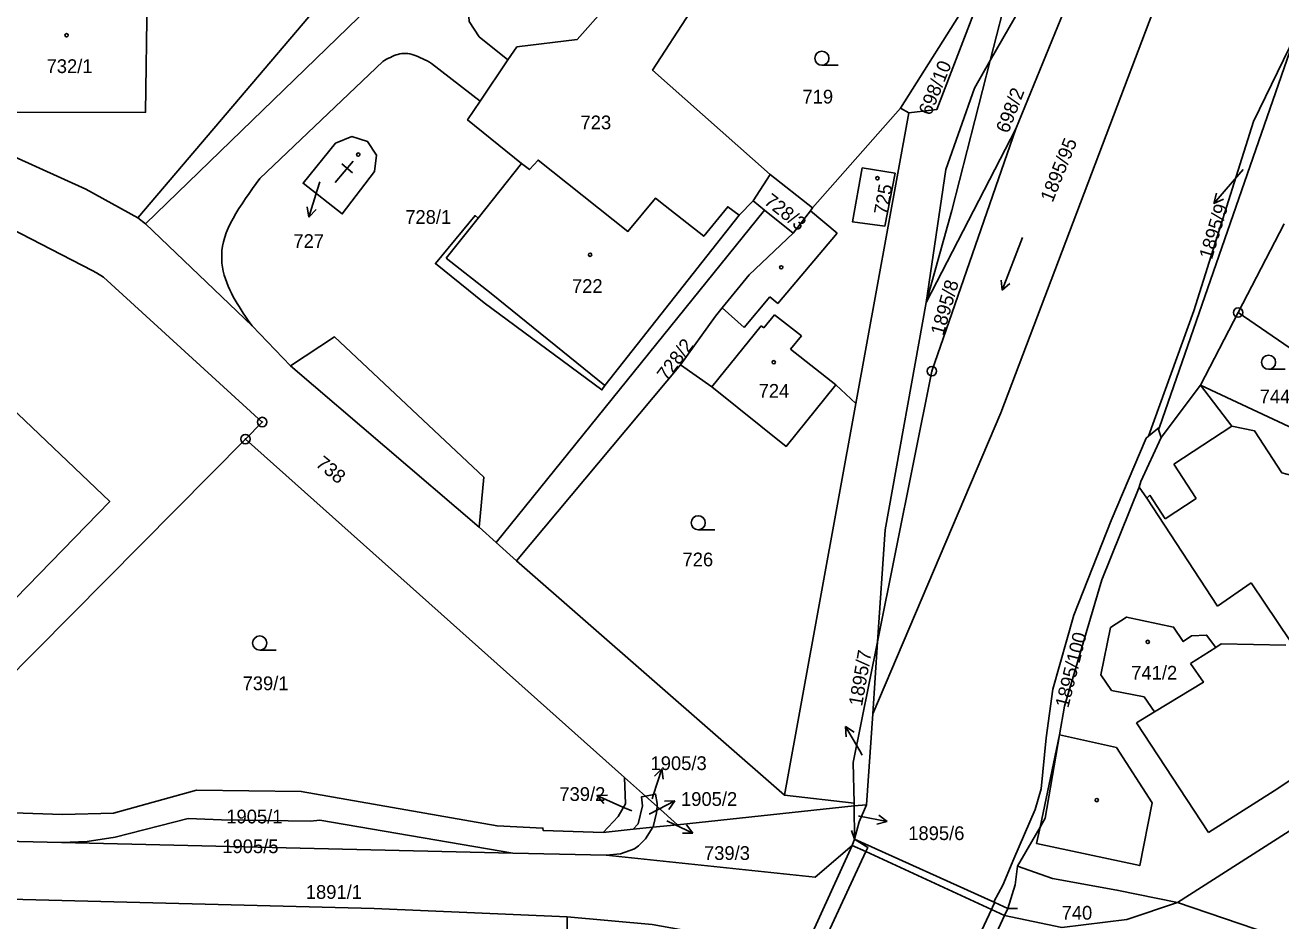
# Model space of a CAD drawing. Extents: x -587171 to -555306, y -1167727 to -1074732.
# Drawn here: x -560966.9 to -560833.4, y -1078357 to -1078261.8 of the extents above; entities that cross this region are included whole.
import ezdxf

# ---------------------------------------------------------------- set-up
doc = ezdxf.new("R2010")
doc.units = 0
for name, color, linetype in [('Hranice parcel', 7, 'Continuous'), ('Parcelní čísla', 7, 'Continuous'), ('Pop  PČ popisy', 7, 'Continuous'), ('Vnitřní kresba', 7, 'Continuous'), ('Značky bodu BP', 7, 'Continuous'), ('Značky budov', 7, 'Continuous'), ('Značky kultur', 7, 'Continuous')]:
    doc.layers.add(name, color=color, linetype=linetype)

msp = doc.modelspace()

# ---------------------------------------------------------------- linework, layer by layer
at = {"layer": 'Hranice parcel'}
for p, q in [((-560873.8, -1078270.61), (-560859.42, -1078247.75)), ((-560861.57, -1078272.8), (-560852.78, -1078251.3)), ((-560936.7, -1078260.89), (-560954.86, -1078282.28)), ((-560831.84, -1078262.87), (-560846.3, -1078304.51)), ((-560883.15, -1078281.2), (-560873.8, -1078270.61)), ((-560878.56, -1078302), (-560872.93, -1078271.11)), ((-560872.93, -1078271.11), (-560873.8, -1078270.61)), ((-560861.57, -1078272.8), (-560871.09, -1078291.27)), ((-560889.47, -1078280.48), (-560887.66, -1078277.67)), ((-560887.66, -1078277.67), (-560883.15, -1078281.2)), ((-560890.95, -1078281.97), (-560889.47, -1078280.48)), ((-560888.28, -1078281.44), (-560889.47, -1078280.48)), ((-560916.78, -1078316.76), (-560888.28, -1078281.44)), ((-560885.23, -1078283.9), (-560888.28, -1078281.44)), ((-560837.93, -1078292.34), (-560833.04, -1078282.89)), ((-560841.92, -1078300.06), (-560837.93, -1078292.34)), ((-560897.18, -1078297.9), (-560914.63, -1078318.72)), ((-560841.92, -1078300.06), (-560846.09, -1078305.62)), ((-560810.03, -1078314.95), (-560841.92, -1078300.06)), ((-560886.14, -1078343.63), (-560878.56, -1078302)), ((-560847.44, -1078305.46), (-560846.3, -1078304.51)), ((-560943.44, -1078305.78), (-560903.14, -1078341.76)), ((-560846.09, -1078305.62), (-560848.28, -1078310.28)), ((-560916.78, -1078316.76), (-560914.63, -1078318.72)), ((-560914.63, -1078318.72), (-560886.14, -1078343.63)), ((-560852.4, -1078320.73), (-560856.39, -1078334.17)), ((-560876.76, -1078334.99), (-560876.25, -1078327.32)), ((-560844.37, -1078355.05), (-560801.81, -1078327.78)), ((-560876.76, -1078334.99), (-560877.41, -1078344.64)), ((-560903.14, -1078341.76), (-560900.93, -1078343.73)), ((-560878.75, -1078344.48), (-560886.14, -1078343.63)), ((-560900.93, -1078343.73), (-560899.68, -1078344.85)), ((-560899.68, -1078344.85), (-560897.53, -1078346.77)), ((-560897.53, -1078346.77), (-560878.75, -1078344.78)), ((-560878.75, -1078344.78), (-560878.75, -1078344.48)), ((-560878.75, -1078344.78), (-560877.41, -1078344.64)), ((-560878.75, -1078344.78), (-560878.69, -1078348.32)), ((-560905.4, -1078347.6), (-560902.21, -1078347.26)), ((-560902.21, -1078347.26), (-560900.13, -1078347.04)), ((-560900.13, -1078347.04), (-560897.53, -1078346.77)), ((-560862.39, -1078355.68), (-560863.77, -1078355.05)), ((-560862.39, -1078355.68), (-560862.76, -1078356.41)), ((-560844.37, -1078355.05), (-560831.14, -1078359.52)), ((-560862.76, -1078356.41), (-560867.32, -1078366.23))]:
    msp.add_line(p, q, dxfattribs=at)
for points in [[(-560876.76, -1078334.99), (-560863.14, -1078303), (-560843.89, -1078252.14), (-560835.48, -1078230.5)], [(-560975.6, -1078271.08), (-560969.5, -1078271.07), (-560954.05, -1078271.05), (-560953.89, -1078258.74), (-560953.94, -1078254.36), (-560962.01, -1078249.46)], [(-560857.54, -1078249.2), (-560865.13, -1078258.18), (-560869.96, -1078270.77), (-560872.93, -1078271.11)], [(-560918.28, -1078255.05), (-560919.83, -1078258.61), (-560919.65, -1078261.4), (-560918.59, -1078263.02), (-560915.56, -1078265.47)], [(-560915.56, -1078265.47), (-560914.58, -1078264.09), (-560908.19, -1078263.31), (-560902.01, -1078256.32), (-560896.18, -1078260.41)], [(-560871.09, -1078291.27), (-560868.35, -1078281.5), (-560864.28, -1078265.55), (-560862.94, -1078260.3), (-560858.64, -1078255.73)], [(-560896.18, -1078260.41), (-560900.17, -1078266.58), (-560887.66, -1078277.67)], [(-560847.44, -1078305.46), (-560842.64, -1078292.16), (-560836.31, -1078272.04), (-560831.84, -1078262.87)], [(-560915.56, -1078265.47), (-560918.47, -1078269.87), (-560919.82, -1078271.87), (-560914.09, -1078276.49)], [(-560975.6, -1078271.08), (-560975.58, -1078272.35), (-560960.38, -1078279.23), (-560954.86, -1078282.28)], [(-560876.25, -1078327.32), (-560870.47, -1078298.56), (-560861.57, -1078272.8)], [(-560933.87, -1078274.34), (-560937.3, -1078278.6), (-560933.14, -1078281.85), (-560929.72, -1078277.35), (-560929.51, -1078275.62), (-560930.45, -1078274.14), (-560932.11, -1078273.63), (-560933.87, -1078274.34)], [(-560914.09, -1078276.49), (-560918.7, -1078282.3), (-560919.03, -1078282.03), (-560923.24, -1078287.14), (-560918.05, -1078291.3), (-560905.55, -1078300.56), (-560905.24, -1078300.1), (-560890.95, -1078281.97)], [(-560890.95, -1078281.97), (-560892.18, -1078281.1), (-560894.73, -1078284.22), (-560898.84, -1078280.99), (-560899.85, -1078280.17), (-560902.78, -1078283.71), (-560912.33, -1078276.14), (-560913.26, -1078277.15), (-560914.09, -1078276.49)], [(-560877.88, -1078276.96), (-560874.38, -1078277.53), (-560875.48, -1078283.16), (-560878.9, -1078282.7), (-560877.88, -1078276.96)], [(-560980.94, -1078278.9), (-560975.34, -1078279.89), (-560974.92, -1078280.03), (-560959.72, -1078287.86), (-560959.25, -1078288.13), (-560958.53, -1078288.59), (-560941.65, -1078303.97), (-560943.44, -1078305.78)], [(-560954.86, -1078282.28), (-560954.07, -1078282.89), (-560942.73, -1078293.75), (-560938.66, -1078298.01), (-560933.98, -1078294.93), (-560918.09, -1078309.84), (-560918.58, -1078315.14), (-560916.78, -1078316.76)], [(-560883.15, -1078281.2), (-560883.39, -1078281.51), (-560885.23, -1078283.9)], [(-560885.23, -1078283.9), (-560889.91, -1078288.32), (-560892.75, -1078291.85), (-560893.46, -1078292.72), (-560897.18, -1078297.9)], [(-560991.5, -1078345.99), (-560990.38, -1078345.81), (-560957.85, -1078312.42), (-560979.66, -1078291.65), (-560986.56, -1078298.77), (-560970.59, -1078314.29), (-560976.42, -1078320.26), (-560989.21, -1078333.37), (-561008.36, -1078315.68), (-561001.24, -1078300.34), (-561005.51, -1078298.23)], [(-560871.09, -1078291.27), (-560875.45, -1078315.42), (-560876.25, -1078327.32)], [(-560837.93, -1078292.34), (-560828.78, -1078298.59), (-560810.03, -1078314.95)], [(-560897.18, -1078297.9), (-560893.86, -1078300.22), (-560885.98, -1078306.57), (-560880.7, -1078300.01), (-560878.56, -1078302)], [(-560811.37, -1078328.88), (-560816.43, -1078331.54), (-560823.11, -1078321.25), (-560824.77, -1078322.33), (-560825.94, -1078320.54), (-560825.02, -1078319.94), (-560825.21, -1078319.65), (-560826.12, -1078320.26), (-560830.32, -1078313.81), (-560829.97, -1078312.53), (-560829.83, -1078312.57), (-560829.7, -1078312.12), (-560831.73, -1078311.54), (-560831.41, -1078310.38), (-560831.28, -1078310.42), (-560831.15, -1078309.95), (-560833.27, -1078309.36), (-560836.18, -1078304.91), (-560838.58, -1078304.42), (-560841.92, -1078300.06)], [(-560846.3, -1078304.51), (-560846.39, -1078304.77), (-560846.09, -1078305.62)], [(-560943.44, -1078305.78), (-560980.48, -1078343.18), (-560981.81, -1078345.03)], [(-560863.77, -1078355.05), (-560863.85, -1078354.91), (-560862.95, -1078353.19), (-560861.78, -1078350.38), (-560859.5, -1078345.14), (-560858.87, -1078342.95), (-560858.34, -1078337.52), (-560857.63, -1078332.36), (-560855.4, -1078324.5), (-560851.41, -1078314.44), (-560847.7, -1078305.67), (-560847.44, -1078305.46)], [(-560848.28, -1078310.28), (-560848.43, -1078310.88), (-560852.4, -1078320.73)], [(-560846.8, -1078334.77), (-560847.93, -1078333.17), (-560851.38, -1078332.5), (-560852.52, -1078330.85), (-560851.51, -1078325.81), (-560849.79, -1078324.7), (-560844.78, -1078325.76), (-560843.76, -1078327.3), (-560842.89, -1078326.69), (-560841.28, -1078326.61), (-560840.31, -1078327.93), (-560842.98, -1078329.63)], [(-560876.25, -1078327.32), (-560878.83, -1078340.15), (-560878.75, -1078344.48)], [(-560842.98, -1078329.63), (-560841.62, -1078331.63), (-560846.8, -1078334.77)], [(-560856.39, -1078334.17), (-560856.91, -1078337.2), (-560858.42, -1078346.07)], [(-560905.4, -1078347.6), (-560903.81, -1078345.91), (-560903.03, -1078344.54), (-560903.14, -1078341.76)], [(-560981.81, -1078345.03), (-560962.87, -1078345.67), (-560957.44, -1078345.55), (-560948.62, -1078343.1), (-560937.51, -1078343.23), (-560916.68, -1078346.89), (-560911.81, -1078347.13), (-560911.8, -1078347.38), (-560905.4, -1078347.6)], [(-560900.93, -1078343.73), (-560899.85, -1078343.51), (-560899.66, -1078344.52), (-560899.68, -1078344.85)], [(-560902.21, -1078347.26), (-560901.7, -1078346.66), (-560901.22, -1078344.78), (-560901.34, -1078343.82), (-560900.93, -1078343.73)], [(-560899.68, -1078344.85), (-560899.73, -1078345.52), (-560900.11, -1078347.01), (-560900.13, -1078347.04)], [(-560877.41, -1078344.64), (-560878.19, -1078346.45), (-560878.69, -1078348.32)], [(-560963, -1078348.67), (-560960.26, -1078348.57), (-560957.28, -1078348.11), (-560949.51, -1078346.12), (-560945.98, -1078346.24), (-560936.53, -1078346.39), (-560935.53, -1078346.29), (-560915.01, -1078349.78)], [(-560858.42, -1078346.07), (-560858.98, -1078347.04), (-560861.37, -1078351.19)], [(-560915.01, -1078349.78), (-560905.1, -1078350.01), (-560903.57, -1078349.86), (-560902.08, -1078349.33), (-560901.66, -1078349.02), (-560900.93, -1078348.26), (-560900.13, -1078347.04)], [(-560986.22, -1078347.96), (-560984.24, -1078348.15), (-560976.6, -1078348.33), (-560963, -1078348.67)], [(-560915.01, -1078349.78), (-560936.14, -1078349.3), (-560963, -1078348.67)], [(-560878.69, -1078348.32), (-560877.29, -1078349.19), (-560877.5, -1078349.63), (-560883.75, -1078363.16), (-560883.95, -1078363.58), (-560884.1, -1078363.92), (-560885.12, -1078366.27), (-560887.52, -1078371.1), (-560889.77, -1078371.49), (-560902.77, -1078373.74)], [(-560878.69, -1078348.32), (-560878.94, -1078348.97), (-560884.6, -1078361.4)], [(-560861.37, -1078351.19), (-560861.63, -1078353.15), (-560862.39, -1078355.68)], [(-560844.37, -1078355.05), (-560850.81, -1078353.71), (-560857.67, -1078352.5), (-560861.37, -1078351.19)], [(-560869.31, -1078370.59), (-560870.63, -1078369.61), (-560870.46, -1078369.24), (-560864.14, -1078355.77), (-560863.91, -1078355.28), (-560863.77, -1078355.05)], [(-560862.76, -1078356.41), (-560856.66, -1078357.68), (-560849.77, -1078356.84), (-560844.37, -1078355.05)], [(-560909.29, -1078359.53), (-560909.25, -1078356.56), (-560900.21, -1078357.39), (-560892.88, -1078358.7), (-560887.14, -1078360.42), (-560884.6, -1078361.4)]]:
    msp.add_lwpolyline(points, dxfattribs=at)
at = {"layer": 'Pop  PČ popisy'}
for p, q in [((-560837.39, -1078277.14), (-560838.54, -1078278.46)), ((-560935.81, -1078279.33), (-560936.69, -1078282.2)), ((-560935.54, -1078278.45), (-560935.81, -1078279.33)), ((-560838.54, -1078278.46), (-560840.51, -1078280.73)), ((-560840.51, -1078280.73), (-560840.23, -1078279.64)), ((-560840.51, -1078280.73), (-560839.47, -1078280.3)), ((-560936.69, -1078282.2), (-560936.87, -1078281.1)), ((-560936.69, -1078282.2), (-560935.92, -1078281.39)), ((-560878.15, -1078338.92), (-560879.65, -1078336.32)), ((-560879.65, -1078336.32), (-560878.72, -1078336.94)), ((-560879.65, -1078336.32), (-560879.58, -1078337.44)), ((-560877.89, -1078339.38), (-560878.15, -1078338.92)), ((-560900.11, -1078343.67), (-560899.18, -1078340.82)), ((-560899.18, -1078340.82), (-560899.97, -1078341.61)), ((-560899.18, -1078340.82), (-560899.02, -1078341.92)), ((-560906.07, -1078343.67), (-560904.95, -1078343.62)), ((-560903.33, -1078344.89), (-560906.07, -1078343.67)), ((-560906.07, -1078343.67), (-560905.36, -1078344.53)), ((-560900.22, -1078344.01), (-560900.11, -1078343.67)), ((-560902.37, -1078345.31), (-560903.33, -1078344.89)), ((-560900.46, -1078345.6), (-560897.79, -1078344.24)), ((-560897.79, -1078344.24), (-560898.91, -1078344.25)), ((-560897.79, -1078344.24), (-560898.45, -1078345.14)), ((-560900.52, -1078345.63), (-560900.46, -1078345.6)), ((-560898.65, -1078346.35), (-560898.59, -1078346.38)), ((-560898.59, -1078346.38), (-560895.87, -1078347.65)), ((-560878.29, -1078345.82), (-560878.18, -1078345.85)), ((-560878.18, -1078345.85), (-560875.23, -1078346.42)), ((-560875.23, -1078346.42), (-560876.12, -1078345.74)), ((-560895.87, -1078347.65), (-560896.99, -1078347.68)), ((-560895.87, -1078347.65), (-560896.57, -1078346.77)), ((-560875.23, -1078346.42), (-560876.31, -1078346.72))]:
    msp.add_line(p, q, dxfattribs=at)
at = {"layer": 'Vnitřní kresba'}
for p, q in [((-560921.31, -1078251.18), (-560954.07, -1078282.89)), ((-560864.28, -1078265.55), (-560858.64, -1078255.73)), ((-560941.89, -1078278.08), (-560928.82, -1078265.64)), ((-560923.65, -1078265.86), (-560918.47, -1078269.87)), ((-560865.96, -1078268.48), (-560864.28, -1078265.55)), ((-560869, -1078277.15), (-560865.96, -1078268.48)), ((-560871.09, -1078291.27), (-560869, -1078277.15)), ((-560922.09, -1078286.57), (-560918.7, -1078282.3)), ((-560883.39, -1078281.51), (-560880.56, -1078283.9)), ((-560880.56, -1078283.9), (-560886.85, -1078291.39)), ((-560917.3, -1078290.31), (-560922.09, -1078286.57)), ((-560905.24, -1078300.1), (-560917.3, -1078290.31)), ((-560887.7, -1078290.68), (-560890.42, -1078293.91)), ((-560886.85, -1078291.39), (-560887.7, -1078290.68)), ((-560890.42, -1078293.91), (-560892.75, -1078291.85)), ((-560888.34, -1078293.97), (-560887.21, -1078292.58)), ((-560887.21, -1078292.58), (-560884.34, -1078294.82)), ((-560893.86, -1078300.22), (-560888.61, -1078293.75)), ((-560888.61, -1078293.75), (-560888.34, -1078293.97)), ((-560884.34, -1078294.82), (-560885.52, -1078296.24)), ((-560885.52, -1078296.24), (-560880.7, -1078300.01)), ((-560938.66, -1078298.01), (-560918.58, -1078315.14)), ((-560844.77, -1078308.44), (-560838.58, -1078304.42)), ((-560842.38, -1078312.1), (-560844.77, -1078308.44)), ((-560847.64, -1078312.05), (-560848.43, -1078310.88)), ((-560847.64, -1078312.05), (-560847.3, -1078311.75)), ((-560840.11, -1078323.55), (-560847.64, -1078312.05)), ((-560847.3, -1078311.75), (-560845.68, -1078314.25)), ((-560845.68, -1078314.25), (-560842.38, -1078312.1)), ((-560836.53, -1078321.06), (-560840.11, -1078323.55)), ((-560832.34, -1078327.35), (-560836.53, -1078321.06)), ((-560840.31, -1078327.93), (-560839.72, -1078327.55)), ((-560839.72, -1078327.55), (-560832.85, -1078327.68)), ((-560848.74, -1078335.95), (-560846.8, -1078334.77)), ((-560848.74, -1078335.95), (-560841.08, -1078347.61)), ((-560858.98, -1078347.04), (-560856.91, -1078337.2)), ((-560856.91, -1078337.2), (-560850.86, -1078338.55)), ((-560834.08, -1078343.16), (-560828.34, -1078339.33)), ((-560841.08, -1078347.61), (-560834.08, -1078343.16)), ((-560879.02, -1078347.37), (-560878.69, -1078348.32)), ((-560859.34, -1078348.75), (-560858.98, -1078347.04)), ((-560882.87, -1078352.33), (-560878.94, -1078348.97)), ((-560877.5, -1078349.63), (-560878.94, -1078348.97)), ((-560863.77, -1078355.05), (-560878.69, -1078348.32)), ((-560882.87, -1078352.33), (-560905.1, -1078350.01)), ((-560864.14, -1078355.77), (-560877.5, -1078349.63)), ((-560929.76, -1078355.69), (-560986.22, -1078354.24)), ((-560909.25, -1078356.56), (-560929.76, -1078355.69)), ((-560861.39, -1078355.68), (-560862.39, -1078355.68)), ((-560862.76, -1078356.41), (-560864.14, -1078355.77))]:
    msp.add_line(p, q, dxfattribs=at)
for points in [[(-560928.82, -1078265.64), (-560928.62, -1078265.53), (-560928.43, -1078265.42), (-560928.23, -1078265.31), (-560928.03, -1078265.22), (-560927.83, -1078265.12), (-560927.63, -1078265.03), (-560927.43, -1078264.96), (-560927.23, -1078264.9), (-560927.02, -1078264.84), (-560926.82, -1078264.81), (-560926.6, -1078264.79), (-560926.39, -1078264.79), (-560926.17, -1078264.81), (-560925.95, -1078264.85), (-560925.73, -1078264.9), (-560925.51, -1078264.97), (-560925.28, -1078265.05), (-560925.05, -1078265.15), (-560924.82, -1078265.25), (-560924.58, -1078265.36), (-560924.35, -1078265.48), (-560924.12, -1078265.6), (-560923.88, -1078265.73), (-560923.65, -1078265.86)], [(-560942.73, -1078293.75), (-560942.97, -1078293.42), (-560943.2, -1078293.08), (-560943.44, -1078292.74), (-560943.67, -1078292.4), (-560943.89, -1078292.05), (-560944.11, -1078291.71), (-560944.33, -1078291.36), (-560944.54, -1078291.01), (-560944.73, -1078290.65), (-560944.92, -1078290.28), (-560945.1, -1078289.91), (-560945.27, -1078289.53), (-560945.42, -1078289.15), (-560945.56, -1078288.75), (-560945.69, -1078288.35), (-560945.79, -1078287.94), (-560945.87, -1078287.51), (-560945.93, -1078287.09), (-560945.96, -1078286.65), (-560945.96, -1078286.21), (-560945.93, -1078285.75), (-560945.87, -1078285.29), (-560945.77, -1078284.82), (-560945.64, -1078284.34), (-560945.47, -1078283.85), (-560945.26, -1078283.35), (-560945.02, -1078282.85), (-560944.74, -1078282.34), (-560944.44, -1078281.81), (-560944.12, -1078281.29), (-560943.78, -1078280.77), (-560943.42, -1078280.23), (-560943.05, -1078279.7), (-560942.67, -1078279.16), (-560942.28, -1078278.62), (-560941.89, -1078278.08)], [(-560859.34, -1078348.75), (-560848.39, -1078351.11), (-560847.07, -1078344.45), (-560850.86, -1078338.55)]]:
    msp.add_lwpolyline(points, dxfattribs=at)
at = {"layer": 'Značky bodu BP'}
for centre, radius in [((-560837.93, -1078292.34), 0.5), ((-560837.93, -1078292.34), 0.0303), ((-560870.47, -1078298.56), 0.5), ((-560870.47, -1078298.56), 0.0303), ((-560941.65, -1078303.97), 0.5), ((-560941.65, -1078303.97), 0.0303), ((-560943.44, -1078305.78), 0.5), ((-560943.44, -1078305.78), 0.0303)]:
    msp.add_circle(centre, radius, dxfattribs=at)
at = {"layer": 'Značky budov'}
for p, q in [((-560931.98, -1078276.23), (-560933.91, -1078278.53)), ((-560933.2, -1078276.52), (-560932.05, -1078277.48))]:
    msp.add_line(p, q, dxfattribs=at)
for centre in [(-560962.44, -1078262.86), (-560931.45, -1078275.55), (-560876.26, -1078278.06), (-560906.8, -1078286.2), (-560886.49, -1078287.53), (-560887.28, -1078297.61), (-560847.53, -1078327.34), (-560852.96, -1078344.16)]:
    msp.add_circle(centre, 0.175, dxfattribs=at)
at = {"layer": 'Značky kultur'}
for p, q in [((-560882.17, -1078266.06), (-560880.42, -1078266.06)), ((-560860.85, -1078284.37), (-560863, -1078289.97)), ((-560863, -1078289.97), (-560863.12, -1078288.88)), ((-560863, -1078289.97), (-560862.18, -1078289.24)), ((-560834.69, -1078298.37), (-560832.94, -1078298.37)), ((-560895.31, -1078315.43), (-560893.56, -1078315.43)), ((-560941.92, -1078328.21), (-560940.17, -1078328.21))]:
    msp.add_line(p, q, dxfattribs=at)
for centre in [(-560882.17, -1078265.31), (-560834.69, -1078297.62), (-560895.31, -1078314.68), (-560941.92, -1078327.46)]:
    msp.add_circle(centre, 0.75, dxfattribs=at)

# ---------------------------------------------------------------- texts
at = {"layer": 'Parcelní čísla'}
for s, p in [('732/1', (-560964.57, -1078266.88)), ('719', (-560884.23, -1078270.12)), ('723', (-560907.82, -1078272.86)), ('728/1', (-560926.45, -1078282.91)), ('727', (-560938.34, -1078285.47)), ('722', (-560908.73, -1078290.25)), ('724', (-560888.89, -1078301.39)), ('744/2', (-560835.64, -1078301.98)), ('726', (-560896.98, -1078319.31)), ('741/2', (-560849.29, -1078331.35)), ('739/1', (-560943.74, -1078332.47)), ('1905/3', (-560900.38, -1078340.96)), ('739/2', (-560910.07, -1078344.24)), ('1905/2', (-560897.14, -1078344.77)), ('1905/1', (-560945.47, -1078346.63)), ('1895/6', (-560872.99, -1078348.4)), ('1905/5', (-560945.89, -1078349.79)), ('739/3', (-560894.7, -1078350.51)), ('1891/1', (-560937.02, -1078354.65)), ('740', (-560856.69, -1078356.86))]:
    msp.add_text(s, height=1.46, dxfattribs=at).set_placement(p)
for s, rotation, p in [('698/10', 68, (-560870.59, -1078271.48)), ('698/2', 69, (-560862.36, -1078273.37)), ('1895/95', 68, (-560857.65, -1078280.71)), ('728/3', 322, (-560888.42, -1078280.71)), ('725', 80, (-560875.22, -1078282.03)), ('1895/9', 73, (-560840.72, -1078286.78)), ('1895/8', 74, (-560869.25, -1078294.86)), ('728/2', 53, (-560898.66, -1078299.72)), ('738', 321, (-560936.07, -1078308.58)), ('1895/100', 76, (-560855.98, -1078334.43)), ('1895/7', 80, (-560877.9, -1078334.24))]:
    msp.add_text(s, height=1.46, rotation=rotation, dxfattribs=at).set_placement(p)

doc.saveas('drawing.dxf')
